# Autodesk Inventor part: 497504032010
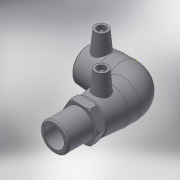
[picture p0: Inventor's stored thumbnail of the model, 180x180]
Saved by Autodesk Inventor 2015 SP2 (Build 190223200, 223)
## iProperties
Created: 2017-06
Part Number: 497504032010
Material: Generic
Description: PE Male Transition Elbow 90° 32x 1
Document SubType Name: Modeling
Designer: KIM
Mass: 147.851 g
Surface Area: 413.375 cm^2
Volume: 147.851 cm^3
Density: 1 g/cm^3
Appearance: Default
Author: KIM
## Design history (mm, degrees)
derived "497504.ipt"
feature "Solid1::497504.ipt"
feature "Solid2::497504.ipt"
tag "TaggingFeature1"
workplane "Work Plane2"
body "Solid1"
body "Solid2"
other parameters: "d2" = 44, "d4" = 26, "d5" = 39.6, "d8" = 168 deg, "d10" = 16, "d11" = 5.33333, "d29" = 43, "d30" = 15, "d31" = 40.56, "d34" = 5 deg, "d41" = 4, "d42" = 14, "d43" = 0, "d48" = 56, "d49" = 32, "d50" = 3.2, "d51" = 16, "d54" = 90 deg, "d86" = 3, "d87" = 0, "d93" = 0.1, "d95" = 33.249, "d96" = 23.2743, "d97" = 24, "d99" = 44, "d100" = 36, "d102" = 1.6, "d106" = 0, "d108" = 36, "d115" = 0, "d_" = 32, "L_" = 118, "D_" = 24, "A_" = 43, "d_2" = 12, "D_1" = 44, "R_" = 33.249
